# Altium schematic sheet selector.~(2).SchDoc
size A4
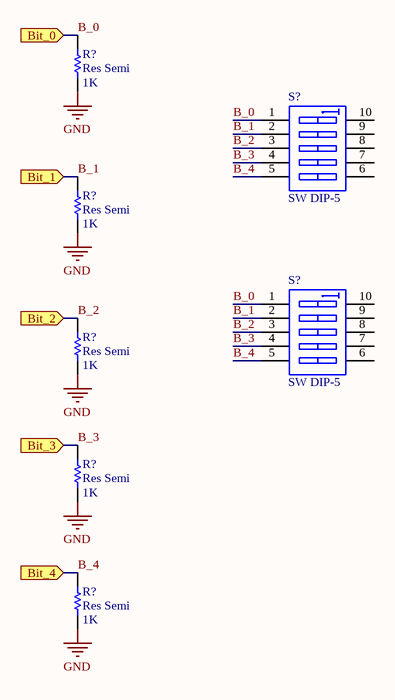
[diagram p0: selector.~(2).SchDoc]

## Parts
(Parts that share a designator on the sheet are numbered #1, #2 ... from top to bottom, then left to right.)
R?#1  Res Semi  value 1K  [2012[0805]]
R?#2  Res Semi  value 1K  [2012[0805]]
R?#3  Res Semi  value 1K  [2012[0805]]
R?#4  Res Semi  value 1K  [2012[0805]]
R?#5  Res Semi  value 1K  [2012[0805]]
S?#1  SW DIP-5  [N10A]
S?#2  SW DIP-5  [N10A]

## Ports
Bit_0 (in), Bit_1 (in), Bit_2 (in), Bit_3 (in), Bit_4 (in)

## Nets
GND: R?#1.1 R?#2.1 R?#3.1 R?#4.1 R?#5.1
B_0: R?#1.2 S?#1.1(A1) S?#2.1(A1) ; port Bit_0
B_1: R?#2.2 S?#1.2(A2) S?#2.2(A2) ; port Bit_1
B_2: R?#3.2 S?#1.3(A3) S?#2.3(A3) ; port Bit_2
B_3: R?#4.2 S?#1.4(A4) S?#2.4(A4) ; port Bit_3
B_4: R?#5.2 S?#1.5(A5) S?#2.5(A5) ; port Bit_4

Not connected (* = marked no-connect by the designer): S?#1 6(B5) 7(B4) 8(B3) 9(B2) 10(B1); S?#2 6(B5) 7(B4) 8(B3) 9(B2) 10(B1)

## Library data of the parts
R?#1-R?#5 = Res Semi: Semiconductor Resistor
S?#1 S?#2 = SW DIP-5: DIP Switch, 5 Position, SPST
